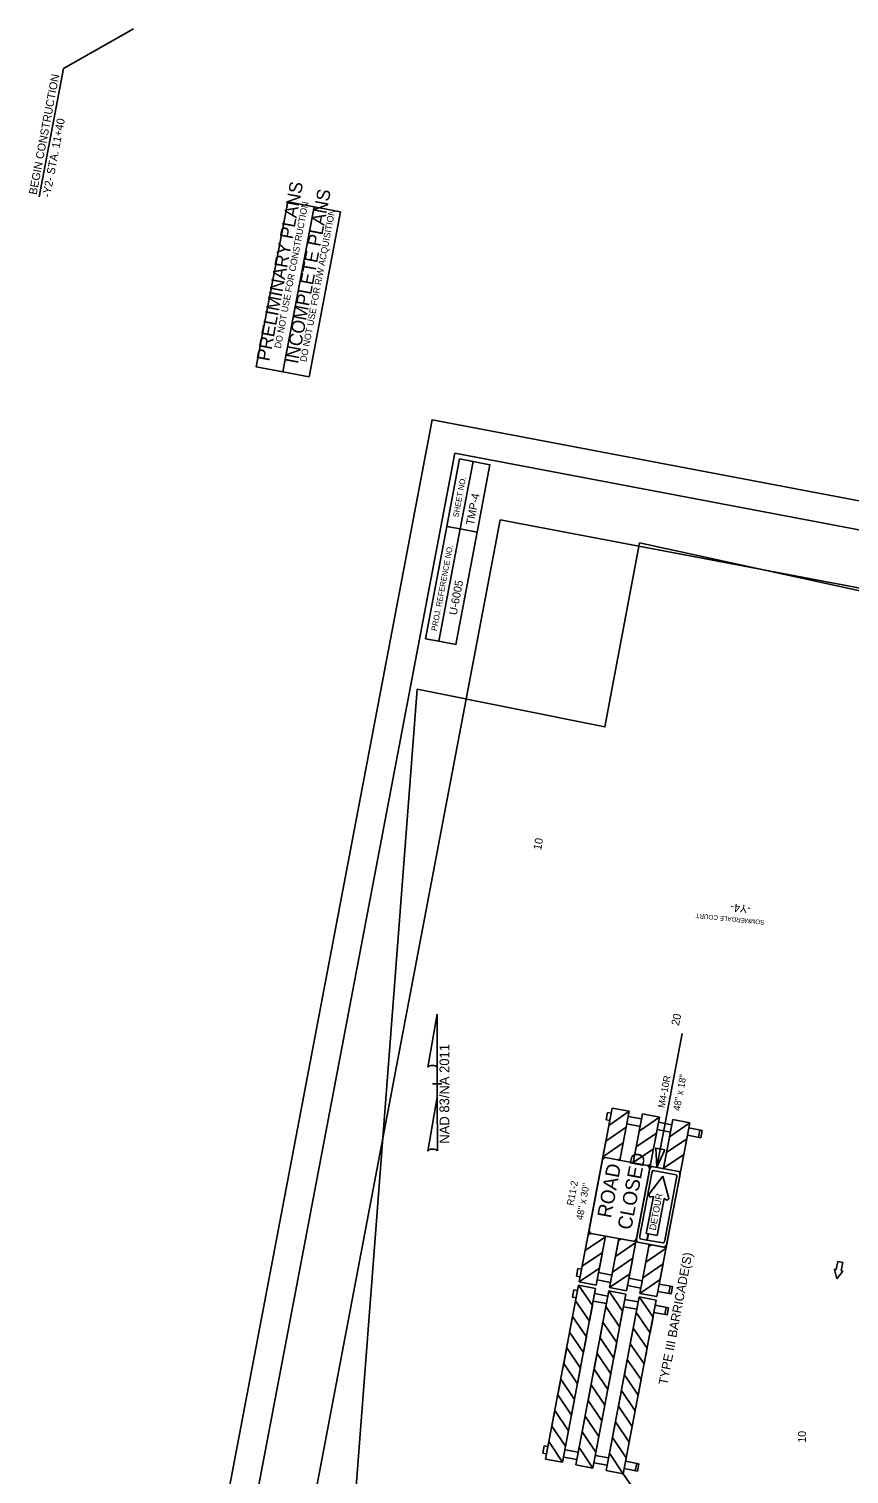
# Model space of a CAD drawing. Extents: x 1615642 to 1617075, y 899305 to 901510.
# Drawn here: x 1615642 to 1616360, y 900246 to 901510 of the extents above; entities that cross this region are included whole.
import ezdxf

# ---------------------------------------------------------------- set-up
doc = ezdxf.new("R2010")
doc.units = 0
for name, color, linetype in [('Default', 7, 'Continuous'), ('DEV BORDER CELL', 7, 'Continuous'), ('DEV DIRECTION OF TRAFFIC FLOW ARROW CELL', 7, 'Continuous'), ('DEV TYPE 3 BARRICADE DOUBLE WITH R11-2 CELL', 7, 'Continuous'), ('DEV TYPE 3 BARRICADE WITH R11-2 M4-10R CELL', 7, 'Continuous'), ('Prop DSN Text', 7, 'Continuous'), ('Prop Horizontal Alignment Tick Label', 7, 'Continuous'), ('Prop North Arrow NAD83 for Plan Sheets CELL', 7, 'Continuous'), ('Scratch_Level_0', 7, 'Continuous'), ('Sheet Clip Boundary CELL', 7, 'Continuous'), ('Sheet Plot Border Outside CELL', 7, 'Continuous'), ('Sheet Sticker Incomplete CELL', 7, 'Continuous'), ('Sheet Sticker Preliminary CELL', 7, 'Continuous')]:
    doc.layers.add(name, color=color, linetype=linetype)

msp = doc.modelspace()

# ---------------------------------------------------------------- linework, layer by layer
at = {"layer": 'DEV BORDER CELL'}
msp.add_line((1616019.4, 901072.8), (1616030.6, 901131.7), dxfattribs=at)
for points in [[(1616014.5, 901139.2), (1615734.7, 899665.5), (1616766.3, 899469.7), (1617046.1, 900943.3)], [(1616019.4, 901072.8), (1616030.6, 901131.7), (1616018.8, 901134), (1616007.6, 901075)], [(1616019.4, 901072.8), (1616030.6, 901131.7), (1616045.3, 901128.9), (1616034.1, 901070)], [(1615988.9, 900976.8), (1616007.6, 901075), (1616019.4, 901072.8), (1616000.7, 900974.5)], [(1616019.4, 901072.8), (1616000.7, 900974.5), (1616015.5, 900971.7), (1616034.1, 901070)]]:
    msp.add_lwpolyline(points, close=True, dxfattribs=at)
at = {"layer": 'DEV DIRECTION OF TRAFFIC FLOW ARROW CELL'}
for p, q in [((1616349.8, 900431.8), (1616348.3, 900424.8)), ((1616354, 900430.9), (1616349.8, 900431.8)), ((1616348.3, 900424.8), (1616346.8, 900425.1)), ((1616346.8, 900425.1), (1616348.7, 900416.7)), ((1616348.7, 900416.7), (1616354, 900423.5)), ((1616352.5, 900423.9), (1616354, 900430.9)), ((1616354, 900423.5), (1616352.5, 900423.9))]:
    msp.add_line(p, q, dxfattribs=at)
at = {"layer": 'DEV TYPE 3 BARRICADE DOUBLE WITH R11-2 CELL'}
for p, q in [((1616152.3, 900566.1), (1616123.4, 900414.1)), ((1616147, 900555.8), (1616148.2, 900562.2)), ((1616148.2, 900562.2), (1616151.4, 900561.6)), ((1616152.3, 900566.1), (1616149.4, 900551)), ((1616149.4, 900551), (1616167.2, 900563.3)), ((1616167.2, 900563.3), (1616152.3, 900566.1)), ((1616167.2, 900563.3), (1616152.3, 900566.1)), ((1616159, 900520.4), (1616167.2, 900563.3)), ((1616164.8, 900406.2), (1616193.7, 900558.3)), ((1616166.3, 900558.8), (1616177.9, 900556.6)), ((1616178.8, 900561.1), (1616170.6, 900518.2)), ((1616178.8, 900561.1), (1616175.9, 900545.9)), ((1616175.9, 900545.9), (1616193.7, 900558.3)), ((1616193.7, 900558.3), (1616178.8, 900561.1)), ((1616193.7, 900558.3), (1616178.8, 900561.1)), ((1616164.5, 900549.4), (1616146.8, 900537.3)), ((1616147, 900555.8), (1616150.2, 900555.2)), ((1616161.9, 900535.7), (1616164.5, 900549.4)), ((1616165.1, 900552.3), (1616176.7, 900550.1)), ((1616191.4, 900401.2), (1616220.2, 900553.2)), ((1616191.6, 900547.3), (1616203.2, 900545.1)), ((1616192.8, 900553.7), (1616204.5, 900551.5)), ((1616205.3, 900556.1), (1616197.2, 900513.2)), ((1616205.3, 900556.1), (1616202.4, 900540.9)), ((1616202.4, 900540.9), (1616220.2, 900553.2)), ((1616220.2, 900553.2), (1616205.3, 900556.1)), ((1616220.2, 900553.2), (1616205.3, 900556.1)), ((1616219.4, 900548.7), (1616231, 900546.5)), ((1616227.8, 900540.4), (1616229, 900546.9)), ((1616229.7, 900540), (1616231, 900546.5)), ((1616146.8, 900537.3), (1616144.2, 900523.6)), ((1616144.2, 900523.6), (1616161.9, 900535.7)), ((1616191, 900544.3), (1616173.3, 900532.2)), ((1616188.5, 900530.6), (1616191, 900544.3)), ((1616217.6, 900539.3), (1616199.8, 900527.2)), ((1616215, 900525.6), (1616217.6, 900539.3)), ((1616218.1, 900542.3), (1616229.7, 900540)), ((1616159.3, 900522), (1616157.5, 900520.7)), ((1616157.5, 900520.7), (1616159, 900520.4)), ((1616159, 900520.4), (1616159.3, 900522)), ((1616173.3, 900532.2), (1616170.7, 900518.6)), ((1616170.7, 900518.6), (1616188.5, 900530.6)), ((1616199.8, 900527.2), (1616197.2, 900513.5)), ((1616197.2, 900513.5), (1616215, 900525.6)), ((1616173.7, 900453), (1616184.8, 900511.5)), ((1616185.9, 900517), (1616183.8, 900515.6)), ((1616184.8, 900511.5), (1616185.9, 900517)), ((1616133.5, 900456.7), (1616131.2, 900455.1)), ((1616131.2, 900455.1), (1616128.6, 900441.5)), ((1616128.6, 900441.5), (1616146.3, 900453.5)), ((1616146.4, 900454.1), (1616134, 900456.5)), ((1616138.3, 900411.3), (1616146.4, 900454.1)), ((1616146.3, 900453.5), (1616146.4, 900454.1)), ((1616158.1, 900451.9), (1616149.9, 900409.1)), ((1616157.7, 900450.1), (1616155.1, 900436.4)), ((1616155.1, 900436.4), (1616172.9, 900448.5)), ((1616159.9, 900451.6), (1616157.7, 900450.1)), ((1616170.6, 900449.6), (1616159.9, 900451.6)), ((1616172.9, 900448.5), (1616173.7, 900452.9)), ((1616184.6, 900446.9), (1616176.4, 900404)), ((1616143.7, 900439.9), (1616126, 900427.8)), ((1616141.1, 900426.2), (1616143.7, 900439.9)), ((1616170.3, 900434.8), (1616152.5, 900422.7)), ((1616167.7, 900421.1), (1616170.3, 900434.8)), ((1616121, 900419.2), (1616122.3, 900425.7)), ((1616121, 900419.2), (1616124.3, 900418.6)), ((1616122.3, 900425.7), (1616125.5, 900425.1)), ((1616126, 900427.8), (1616123.4, 900414.1)), ((1616123.4, 900414.1), (1616141.1, 900426.2)), ((1616140.4, 900422.2), (1616152, 900420)), ((1616152.5, 900422.7), (1616149.9, 900409.1)), ((1616149.9, 900409.1), (1616167.7, 900421.1)), ((1616196.8, 900429.8), (1616179, 900417.7)), ((1616194.2, 900416.1), (1616196.8, 900429.8)), ((1616094, 900259.1), (1616122.8, 900411.1)), ((1616137.7, 900408.3), (1616108.9, 900256.3)), ((1616118.8, 900407.2), (1616117.5, 900400.8)), ((1616118.8, 900407.2), (1616122, 900406.6)), ((1616120.2, 900397.5), (1616122.8, 900411.1)), ((1616120.5, 900254.1), (1616149.4, 900406.1)), ((1616122.8, 900411.1), (1616137.7, 900408.3)), ((1616122.8, 900411.1), (1616134.9, 900393.4)), ((1616123.4, 900414.1), (1616138.3, 900411.3)), ((1616139.2, 900415.8), (1616150.8, 900413.6)), ((1616146.8, 900392.4), (1616149.4, 900406.1)), ((1616149.4, 900406.1), (1616164.3, 900403.3)), ((1616149.4, 900406.1), (1616161.4, 900388.4)), ((1616149.9, 900409.1), (1616164.8, 900406.2)), ((1616165.7, 900410.8), (1616177.3, 900408.5)), ((1616166.9, 900417.2), (1616178.5, 900415)), ((1616179, 900417.7), (1616176.4, 900404)), ((1616176.4, 900404), (1616194.2, 900416.1)), ((1616193.4, 900412.2), (1616205, 900410)), ((1616201.9, 900403.9), (1616203.1, 900410.3)), ((1616203.8, 900403.5), (1616205, 900410)), ((1616117.5, 900400.8), (1616120.8, 900400.2)), ((1616132.3, 900379.7), (1616120.2, 900397.5)), ((1616164.3, 900403.3), (1616135.4, 900251.2)), ((1616135.7, 900397.3), (1616147.3, 900395.1)), ((1616136.9, 900403.8), (1616148.5, 900401.6)), ((1616147, 900249), (1616175.9, 900401.1)), ((1616190.8, 900398.2), (1616161.9, 900246.2)), ((1616163.4, 900398.7), (1616175, 900396.5)), ((1616173.3, 900387.4), (1616175.9, 900401.1)), ((1616175.9, 900401.1), (1616188, 900383.3)), ((1616175.9, 900401.1), (1616190.8, 900398.2)), ((1616176.4, 900404), (1616191.4, 900401.2)), ((1616189.9, 900393.7), (1616201.5, 900391.5)), ((1616192.2, 900405.7), (1616203.8, 900403.5)), ((1616115, 900370.1), (1616117.6, 900383.8)), ((1616117.6, 900383.8), (1616129.7, 900366)), ((1616134.9, 900393.4), (1616132.3, 900379.7)), ((1616158.8, 900374.7), (1616146.8, 900392.4)), ((1616161.4, 900388.4), (1616158.8, 900374.7)), ((1616162.2, 900392.3), (1616173.8, 900390.1)), ((1616185.4, 900369.6), (1616173.3, 900387.4)), ((1616188, 900383.3), (1616185.4, 900369.6)), ((1616188.7, 900387.3), (1616200.3, 900385.1)), ((1616199.6, 900391.9), (1616198.4, 900385.4)), ((1616201.5, 900391.5), (1616200.3, 900385.1)), ((1616127.1, 900352.4), (1616115, 900370.1)), ((1616141.6, 900365.1), (1616144.2, 900378.7)), ((1616144.2, 900378.7), (1616156.2, 900361)), ((1616168.1, 900360), (1616170.7, 900373.7)), ((1616170.7, 900373.7), (1616182.8, 900356)), ((1616109.9, 900342.7), (1616112.5, 900356.4)), ((1616112.5, 900356.4), (1616124.5, 900338.7)), ((1616129.7, 900366), (1616127.1, 900352.4)), ((1616153.6, 900347.3), (1616141.6, 900365.1)), ((1616156.2, 900361), (1616153.6, 900347.3)), ((1616180.2, 900342.3), (1616168.1, 900360)), ((1616182.8, 900356), (1616180.2, 900342.3)), ((1616136.4, 900337.7), (1616139, 900351.4)), ((1616139, 900351.4), (1616151, 900333.6)), ((1616162.9, 900332.7), (1616165.5, 900346.3)), ((1616165.5, 900346.3), (1616177.6, 900328.6)), ((1616121.9, 900325), (1616109.9, 900342.7)), ((1616124.5, 900338.7), (1616121.9, 900325)), ((1616148.4, 900320), (1616136.4, 900337.7)), ((1616151, 900333.6), (1616148.4, 900320)), ((1616175, 900314.9), (1616162.9, 900332.7)), ((1616104.6, 900315.3), (1616107.2, 900329)), ((1616107.2, 900329), (1616119.3, 900311.3)), ((1616131.2, 900310.3), (1616133.8, 900324)), ((1616133.8, 900324), (1616145.8, 900306.2)), ((1616157.7, 900305.2), (1616160.3, 900318.9)), ((1616160.3, 900318.9), (1616172.4, 900301.2)), ((1616177.6, 900328.6), (1616175, 900314.9)), ((1616116.7, 900297.6), (1616104.6, 900315.3)), ((1616119.3, 900311.3), (1616116.7, 900297.6)), ((1616143.2, 900292.5), (1616131.2, 900310.3)), ((1616145.8, 900306.2), (1616143.2, 900292.5)), ((1616169.8, 900287.5), (1616157.7, 900305.2)), ((1616099.5, 900287.9), (1616102, 900301.6)), ((1616102, 900301.6), (1616114.1, 900283.9)), ((1616126, 900282.9), (1616128.6, 900296.6)), ((1616128.6, 900296.6), (1616140.6, 900278.9)), ((1616172.4, 900301.2), (1616169.8, 900287.5)), ((1616111.5, 900270.2), (1616099.5, 900287.9)), ((1616114.1, 900283.9), (1616111.5, 900270.2)), ((1616138, 900265.2), (1616126, 900282.9)), ((1616152.5, 900277.9), (1616155.1, 900291.6)), ((1616155.1, 900291.6), (1616167.2, 900273.8)), ((1616092.8, 900270.7), (1616091.6, 900264.2)), ((1616092.8, 900270.7), (1616096.1, 900270.1)), ((1616094, 900259.1), (1616096.9, 900274.3)), ((1616096.9, 900274.3), (1616108.9, 900256.3)), ((1616111, 900267.2), (1616122.6, 900265)), ((1616120.5, 900254.1), (1616123.4, 900269.2)), ((1616123.4, 900269.2), (1616135.4, 900251.2)), ((1616140.6, 900278.9), (1616138, 900265.2)), ((1616164.6, 900260.1), (1616152.5, 900277.9)), ((1616167.2, 900273.8), (1616164.6, 900260.1)), ((1616091.6, 900264.2), (1616094.8, 900263.6)), ((1616108.9, 900256.3), (1616094, 900259.1)), ((1616108.9, 900256.3), (1616094, 900259.1)), ((1616109.7, 900260.8), (1616121.4, 900258.6)), ((1616136.3, 900255.8), (1616147.9, 900253.6)), ((1616137.5, 900262.2), (1616149.1, 900260)), ((1616147, 900249), (1616149.9, 900264.2)), ((1616149.9, 900264.2), (1616161.9, 900246.2)), ((1616164, 900257.2), (1616175.6, 900255)), ((1616173.7, 900255.3), (1616172.5, 900248.9)), ((1616175.6, 900255), (1616174.4, 900248.5)), ((1616135.4, 900251.2), (1616120.5, 900254.1)), ((1616135.4, 900251.2), (1616120.5, 900254.1)), ((1616161.9, 900246.2), (1616147, 900249)), ((1616161.9, 900246.2), (1616147, 900249)), ((1616162.8, 900250.7), (1616174.4, 900248.5))]:
    msp.add_line(p, q, dxfattribs=at)
for points in [[(1616183.1, 900515.8), (1616146.5, 900522.8)], [(1616143.4, 900519.4), (1616132.3, 900460.8)], [(1616134, 900456.5), (1616170.6, 900449.6)]]:
    msp.add_lwpolyline(points, dxfattribs=at)
for centre, major_axis, start_param, end_param in [((1616145.8, 900518.9), (0.73, 3.87), 0, 1.571024), ((1616182.4, 900512), (0.73, 3.87), 4.712162, 6.283185), ((1616182.4, 900512), (0.73, 3.87), 4.712497, 5.996053), ((1616134.7, 900460.4), (-0.73, -3.87), 4.712389, 6.283185), ((1616134.7, 900460.4), (-0.73, -3.87), 6.074789, 6.283185), ((1616171.3, 900453.4), (0.73, 3.87), 3.141593, 4.712389), ((1616171.3, 900453.4), (-0.73, -3.87), 0, 1.570796)]:
    msp.add_ellipse(centre, major_axis=major_axis, ratio=0.625, start_param=start_param, end_param=end_param, dxfattribs=at)
at = {"layer": 'DEV TYPE 3 BARRICADE WITH R11-2 M4-10R CELL'}
for p, q in [((1616191.4, 900514.3), (1616213.6, 900631.3)), ((1616186.9, 900509.2), (1616176.4, 900454.5)), ((1616208.2, 900507.7), (1616188.1, 900511.5)), ((1616185, 900491.4), (1616196.6, 900506.5)), ((1616196.6, 900506.5), (1616201.6, 900488.2)), ((1616198.2, 900450.4), (1616208.6, 900505.1)), ((1616211.3, 900506.5), (1616200.2, 900447.9)), ((1616182.1, 900456.5), (1616188.3, 900488.9)), ((1616188.3, 900488.9), (1616186, 900488.4)), ((1616197.7, 900487.1), (1616191.6, 900454.7)), ((1616199.7, 900485.8), (1616197.7, 900487.1)), ((1616176.8, 900451.8), (1616182.7, 900450.7)), ((1616184.2, 900445.1), (1616181.6, 900431.4)), ((1616183.7, 900456.2), (1616182.1, 900456.5)), ((1616182.7, 900450.7), (1616183.7, 900456.2)), ((1616183.9, 900456.2), (1616182.9, 900450.7)), ((1616182.9, 900450.7), (1616196.9, 900448.1)), ((1616191.6, 900454.7), (1616183.9, 900456.2)), ((1616186.4, 900446.6), (1616184.2, 900445.1)), ((1616197.1, 900444.5), (1616186.4, 900446.6)), ((1616199.4, 900443.5), (1616200.2, 900447.9)), ((1616181.6, 900431.4), (1616199.4, 900443.5))]:
    msp.add_line(p, q, dxfattribs=at)
msp.add_lwpolyline([(1616198.4, 900529.7), (1616191.4, 900514.3), (1616190.4, 900531.2)], close=True, dxfattribs=at)
msp.add_lwpolyline([(1616198.4, 900529.7), (1616191.4, 900514.3), (1616190.4, 900531.2)], close=True, dxfattribs=at)
for points in [[(1616173.7, 900453), (1616184.8, 900511.5)], [(1616187, 900515.1), (1616210.6, 900510.6)], [(1616198, 900444.3), (1616174.4, 900448.8)]]:
    msp.add_lwpolyline(points, dxfattribs=at)
for centre, major_axis, ratio, start_param, end_param in [((1616186.3, 900511.2), (0.73, 3.87), 0.375009, 0, 1.570796), ((1616187.7, 900509.1), (0.47, 2.49), 0.337508, 6.283178, 7.854173), ((1616207.8, 900505.3), (0.47, 2.49), 0.337508, 4.712203, 6.283178), ((1616209.9, 900506.8), (-0.73, -3.87), 0.375009, 1.570796, 3.141593), ((1616185.9, 900490.1), (0.34, 1.78), 0.720018, 0.96961, 3.452569), ((1616200.4, 900487.4), (0.34, 1.78), 0.720018, 2.830617, 5.313577), ((1616175.2, 900452.7), (-0.73, -3.87), 0.375009, 4.712162, 6.283185), ((1616177.3, 900454.4), (-0.47, -2.49), 0.337508, 4.712581, 6.283188), ((1616197.4, 900450.6), (-0.47, -2.49), 0.337508, 0.000003, 1.57061), ((1616197.8, 900448.4), (0.73, 3.87), 0.625, 3.141593, 4.712389), ((1616198.8, 900448.2), (-0.73, -3.87), 0.375009, 0, 1.570796)]:
    msp.add_ellipse(centre, major_axis=major_axis, ratio=ratio, start_param=start_param, end_param=end_param, dxfattribs=at)
at = {"layer": 'Prop DSN Text'}
for p, q in [((1615733.5, 901510.3), (1615672.2, 901475.5)), ((1615651, 901363.5), (1615672.2, 901475.5)), ((1616161.9, 900246.2), (1616265.1, 900098.7))]:
    msp.add_line(p, q, dxfattribs=at)
at = {"layer": 'Prop North Arrow NAD83 for Plan Sheets CELL'}
for p, q in [((1615991, 900602), (1615999.2, 900648.3)), ((1615999.2, 900648.3), (1615999.2, 900648.3)), ((1615999.2, 900648.3), (1615999.2, 900648.3)), ((1615999.2, 900648.3), (1615999.2, 900600.5)), ((1615999.2, 900575.7), (1615999.2, 900601.9)), ((1615999.2, 900600.5), (1615999.2, 900601.9)), ((1615998.8, 900587.3), (1615995.2, 900587.3)), ((1615995.2, 900587.3), (1615995.2, 900587.3)), ((1615995.3, 900587.3), (1616003.3, 900587.3)), ((1615999.2, 900575.7), (1615990.9, 900528.5)), ((1615999.3, 900528.7), (1615999.2, 900575.7))]:
    msp.add_line(p, q, dxfattribs=at)
for centre, start_param, end_param in [((1615995.1, 900601.5), 0.216388, 2.908219), ((1615995.1, 900528.3), 0.201328, 3.141593)]:
    msp.add_ellipse(centre, major_axis=(4.23, -0.03), ratio=0.461098, start_param=start_param, end_param=end_param, dxfattribs=at)
at = {"layer": 'Scratch_Level_0'}
msp.add_lwpolyline([(1616054.3, 901080.8), (1615793.2, 899705.3), (1616726.5, 899528.1), (1616890.5, 900391.5), (1616774.3, 900413.6), (1616871.5, 900925.6)], close=True, dxfattribs=at)
at = {"layer": 'Sheet Clip Boundary CELL'}
msp.add_lwpolyline([(1616176.3, 901060.7), (1616913.8, 900900), (1616896.3, 900812.9), (1616872.9, 900688.2), (1616835.9, 900695.2), (1616753.9, 900262.2), (1616898.1, 900233.4), (1616663.9, 899565.7), (1616252.6, 899604), (1615894.7, 899796.7), (1615981.6, 900932.5), (1616145.9, 900899.6)], close=True, dxfattribs=at)
at = {"layer": 'Sheet Plot Border Outside CELL'}
for points in [[(1616760.5, 899304.9), (1615679.8, 899510.1), (1615994.7, 901168.4), (1617075.3, 900963.2)], [(1616760.5, 899304.9), (1617075.3, 900963.2), (1615994.7, 901168.4), (1615679.8, 899510.1)]]:
    msp.add_lwpolyline(points, close=True, dxfattribs=at)
at = {"layer": 'Sheet Sticker Incomplete CELL'}
msp.add_lwpolyline([(1615887.1, 901205.8), (1615864, 901210.2), (1615891.4, 901354.6), (1615914.5, 901350.2)], close=True, dxfattribs=at)
at = {"layer": 'Sheet Sticker Preliminary CELL'}
msp.add_lwpolyline([(1615864, 901210.2), (1615840.9, 901214.5), (1615868.4, 901359), (1615891.4, 901354.6)], close=True, dxfattribs=at)

# ---------------------------------------------------------------- texts
at = {"layer": 'Default'}
msp.add_text('SOMMERDALE COURT', height=4, rotation=174.359, dxfattribs=at).set_placement((1616285.6, 900730.5))
at = {"layer": 'DEV BORDER CELL'}
for s, height, rotation, p in [('SHEET NO.', 5, 79.2499, (1616017.7, 901082.6)), ('TMP-4', 7, 79.2494, (1616031.1, 901075.6)), ('PROJ. REFERENCE NO.', 4.999, 79.2499, (1615998.8, 900983.2)), ('U-6005', 7, 79.2494, (1616016.2, 900997))]:
    msp.add_text(s, height=height, rotation=rotation, dxfattribs=at).set_placement(p)
at = {"layer": 'DEV TYPE 3 BARRICADE DOUBLE WITH R11-2 CELL'}
for s, height, p in [('CLOSED', 12.37, (1616168.9, 900459)), ('ROAD', 12.37, (1616151.2, 900469.3)), ('R11-2', 6, (1616118.3, 900480.4)), ("48'' x 30''", 6, (1616126.5, 900467.9)), ('TYPE III BARRICADE(S)', 7.882, (1616200.5, 900323.4))]:
    msp.add_text(s, height=height, rotation=79.2494, dxfattribs=at).set_placement(p)
at = {"layer": 'DEV TYPE 3 BARRICADE WITH R11-2 M4-10R CELL'}
for s, height, p in [('M4-10R', 6, (1616198.1, 900565.9)), ('48" x 18"', 6, (1616211.4, 900563.4)), ('DETOUR', 5.8, (1616190.3, 900458.8))]:
    msp.add_text(s, height=height, rotation=79.2494, dxfattribs=at).set_placement(p)
at = {"layer": 'Prop DSN Text'}
for s, p in [('BEGIN CONSTRUCTION', (1615648.7, 901364.8)), ('-Y2- STA. 11+40', (1615660.5, 901362.5))]:
    msp.add_text(s, height=7, rotation=79.2493, dxfattribs=at).set_placement(p)
at = {"layer": 'Prop Horizontal Alignment Tick Label'}
for s, rotation, p in [('10', 79.16, (1616090, 900791.5)), ('-Y4-', 174.4938, (1616273.7, 900743.5)), ('20', 77.7098, (1616210.6, 900637.8)), ('10', 88.5681, (1616321.7, 900273.2))]:
    msp.add_text(s, height=7, rotation=rotation, dxfattribs=at).set_placement(p)
at = {"layer": 'Prop North Arrow NAD83 for Plan Sheets CELL'}
msp.add_text('NAD 83/NA 2011', height=8.5, rotation=90, dxfattribs=at).set_placement((1616009.7, 900535))
at = {"layer": 'Sheet Sticker Incomplete CELL'}
for s, height, p in [('INCOMPLETE PLANS', 11.52, (1615877.3, 901216.7)), ('DO NOT USE FOR R/W ACQUISITION', 5.76, (1615884.7, 901218.6))]:
    msp.add_text(s, height=height, rotation=79.2494, dxfattribs=at).set_placement(p)
at = {"layer": 'Sheet Sticker Preliminary CELL'}
for s, height, p in [('PRELIMINARY PLANS', 11.52, (1615852.3, 901219)), ('DO NOT USE FOR CONSTRUCTION', 5.76, (1615862.3, 901230.4))]:
    msp.add_text(s, height=height, rotation=79.2494, dxfattribs=at).set_placement(p)

doc.saveas('drawing.dxf')
